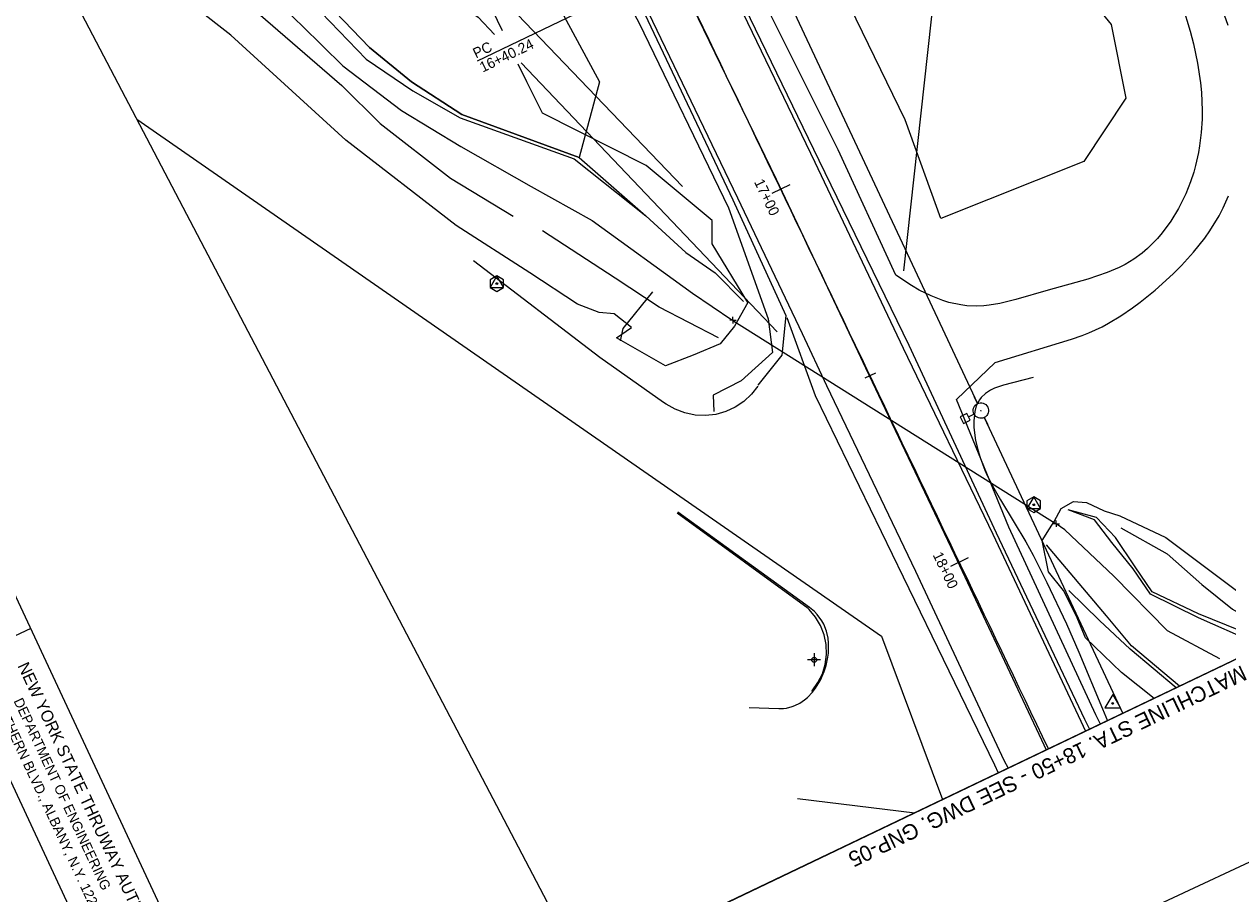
# Model space of a CAD drawing. Extents: x 1040814 to 1041501, y 1126274 to 1127077.
# Drawn here: x 1041061 to 1041352.2, y 1126413.6 to 1126623.9 of the extents above; entities that cross this region are included whole.
import ezdxf

# ---------------------------------------------------------------- set-up
doc = ezdxf.new("R2010")
doc.units = 0
for name, color, linetype in [('AC_P', 7, 'Continuous'), ('ACSC_P_T', 7, 'Continuous'), ('ACSCT_P', 7, 'Continuous'), ('ACSR_P_T', 7, 'Continuous'), ('ACSRT_P', 7, 'Continuous'), ('CBP', 7, 'Continuous'), ('CBS', 7, 'Continuous'), ('clip boundary', 7, 'Continuous'), ('DCP', 7, 'Continuous'), ('DD', 7, 'Continuous'), ('DINV', 7, 'Continuous'), ('LABL', 7, 'Continuous'), ('LAWA', 7, 'Continuous'), ('LAWE', 7, 'Continuous'), ('LELB', 7, 'Continuous'), ('LUKL', 7, 'Continuous'), ('MHB', 7, 'Continuous'), ('NML_P', 7, 'Continuous'), ('NML_P_T', 7, 'Continuous'), ('PE', 7, 'Continuous'), ('PELB', 7, 'Continuous'), ('PSU', 7, 'Continuous'), ('RC', 7, 'Continuous'), ('RDU', 7, 'Continuous'), ('RGB', 7, 'Continuous'), ('S', 7, 'Continuous'), ('SHEET_BORDER', 7, 'Continuous'), ('STDSW', 7, 'Continuous'), ('STDSY', 7, 'Continuous'), ('STFBY', 7, 'Continuous'), ('STSEW', 7, 'Continuous'), ('UEO', 7, 'Continuous'), ('UPL', 7, 'Continuous'), ('USA', 7, 'Continuous')]:
    doc.layers.add(name, color=color, linetype=linetype)

msp = doc.modelspace()

# ---------------------------------------------------------------- linework, layer by layer
at = {"layer": 'AC_P'}
msp.add_arc((951081.07, 1083333.02), 100000, 25.5409537, 25.6611361, dxfattribs=at)
at = {"layer": 'ACSCT_P'}
msp.add_lwpolyline([(1041218.17, 1126637.8), (1041170.58, 1126614.93)], dxfattribs=at)
at = {"layer": 'ACSRT_P'}
for points in [[(1041246.2, 1126584.96), (1041241.87, 1126582.89)], [(1041266.94, 1126539.46), (1041264.35, 1126538.22)], [(1041289.4, 1126494.78), (1041285.07, 1126492.71)], [(1041310.11, 1126449.25), (1041307.51, 1126448.01)]]:
    msp.add_lwpolyline(points, dxfattribs=at)
at = {"layer": 'CBP'}
for points in [[(1041324.33, 1126461.81), (1041322.44, 1126458.54)], [(1041326.22, 1126458.54), (1041324.33, 1126461.81)], [(1041322.44, 1126458.54), (1041326.22, 1126458.54)]]:
    msp.add_lwpolyline(points, dxfattribs=at)
msp.add_circle((1041324.33, 1126459.63), 0.226, dxfattribs=at)
at = {"layer": 'CBS'}
for points in [[(1041175.36, 1126559.22), (1041177, 1126560.17), (1041177, 1126562.06), (1041175.36, 1126563), (1041173.72, 1126562.06), (1041173.72, 1126560.17)], [(1041177, 1126560.17), (1041175.36, 1126563), (1041173.72, 1126560.17)], [(1041305.23, 1126505.78), (1041306.87, 1126506.73), (1041306.87, 1126508.62), (1041305.23, 1126509.56), (1041303.6, 1126508.62), (1041303.6, 1126506.73)], [(1041306.87, 1126506.73), (1041305.23, 1126509.56), (1041303.6, 1126506.73)]]:
    msp.add_lwpolyline(points, close=True, dxfattribs=at)
for centre in [(1041175.36, 1126561.11), (1041305.23, 1126507.67)]:
    msp.add_circle(centre, 0.226, dxfattribs=at)
at = {"layer": 'clip boundary'}
msp.add_lwpolyline([(1041214.88, 1127013.05), (1041436.47, 1126509.64), (1041196.3, 1126394.87), (1040940.57, 1126882.48)], close=True, dxfattribs=at)
at = {"layer": 'DCP'}
msp.add_line((1041232.47, 1126552.24), (1041310.68, 1126503.03), dxfattribs=at)
at = {"layer": 'DD'}
for points in [[(1041074.5, 1126665.52), (1041099.79, 1126648.57), (1041116.42, 1126634.8), (1041128.28, 1126623.45), (1041138.07, 1126613.79), (1041152.29, 1126603.01), (1041166.68, 1126594.25), (1041183.67, 1126584.56), (1041198.44, 1126576.41), (1041222.65, 1126558.83), (1041232.19, 1126552.4)], [(1041312.79, 1126501.59), (1041310.66, 1126503.07)], [(1041350.29, 1126470.43), (1041337.59, 1126477.16), (1041324.61, 1126490.39), (1041312.79, 1126501.59)]]:
    msp.add_lwpolyline(points, dxfattribs=at)
at = {"layer": 'DINV'}
for p, q in [((1041232.47, 1126552.26), (1041231.68, 1126552.26)), ((1041232.47, 1126552.26), (1041232.47, 1126553.05)), ((1041232.47, 1126552.26), (1041233.26, 1126552.26)), ((1041232.47, 1126552.26), (1041232.47, 1126551.48)), ((1041310.66, 1126503.07), (1041310.66, 1126503.85)), ((1041310.66, 1126503.07), (1041309.88, 1126503.07)), ((1041310.66, 1126503.07), (1041311.45, 1126503.07)), ((1041310.66, 1126503.07), (1041310.66, 1126502.28))]:
    msp.add_line(p, q, dxfattribs=at)
at = {"layer": 'LABL'}
msp.add_lwpolyline([(1041253.69, 1126924.89), (1041255.63, 1126894.49), (1041242.19, 1126881.78), (1041242.38, 1126861.25), (1041264.14, 1126852.24), (1041270.04, 1126822.23), (1041258.62, 1126789.97), (1041262.73, 1126771.99), (1041287.02, 1126754.4), (1041303.65, 1126708.97), (1041290.01, 1126684.68), (1041304.47, 1126647.7), (1041323.95, 1126623.76), (1041327.51, 1126605.97), (1041317.37, 1126590.62), (1041282.77, 1126576.87), (1041274.13, 1126600.75), (1041251.99, 1126646.31)], dxfattribs=at)
at = {"layer": 'LAWA'}
for points in [[(1040981.59, 1126825.54), (1041056.77, 1126732.84), (1041104.86, 1126716.99), (1041144.53, 1126704.03), (1041174.4, 1126657.67), (1041200.18, 1126609.9)], [(1041200.18, 1126609.9), (1041195.26, 1126591.63), (1041166.9, 1126602.04), (1041154.69, 1126609.92), (1041144.51, 1126618.19), (1041121.72, 1126641.95), (1041105.83, 1126655.68), (1041077.14, 1126671.62)], [(1041334.37, 1126460.85), (1041326.46, 1126467.11)]]:
    msp.add_lwpolyline(points, dxfattribs=at)
at = {"layer": 'LAWE'}
for points in [[(1041076.45, 1126670.59), (1041104.56, 1126654.96), (1041119.81, 1126640.32), (1041143.71, 1126615.37), (1041155, 1126607.76), (1041166.45, 1126601.18), (1041194.08, 1126591.25), (1041211.38, 1126577.5), (1041221.09, 1126568.66), (1041228.18, 1126563.73), (1041234.99, 1126556.76)], [(1041071.75, 1126659.42), (1041096.69, 1126644.66), (1041137.84, 1126608.98), (1041147.12, 1126599.84), (1041164.12, 1126586.62), (1041179.28, 1126577.39)], [(1041228.94, 1126548.01), (1041214.65, 1126555.44), (1041203.97, 1126562.4), (1041186.38, 1126573.87)], [(1041358.27, 1126474.52), (1041345.09, 1126480.29), (1041333.52, 1126486.04), (1041329.31, 1126492.15), (1041324.1, 1126498.5), (1041319.97, 1126503.98), (1041313.58, 1126506.41)], [(1041340.49, 1126463.77), (1041328.85, 1126473.52), (1041322.86, 1126480.82), (1041308.3, 1126497.94)]]:
    msp.add_lwpolyline(points, dxfattribs=at)
at = {"layer": 'LELB'}
for points in [[(1041220.28, 1126584.56), (1041174.66, 1126632.23), (1041154.91, 1126677.31), (1041125.07, 1126696.32)], [(1041176.7, 1126622.27), (1041171.98, 1126632.18), (1041160.76, 1126642.2), (1041142.54, 1126665.23), (1041113.63, 1126673.96), (1041085.87, 1126690.6)], [(1041077.14, 1126671.62), (1041105.83, 1126655.68), (1041121.72, 1126641.95), (1041144.51, 1126618.19), (1041154.69, 1126609.92), (1041166.9, 1126602.04), (1041195.26, 1126591.63), (1041211.38, 1126577.5), (1041221.09, 1126568.66), (1041228.18, 1126563.73), (1041234.99, 1126556.76)], [(1041236.11, 1126556.56), (1041232.82, 1126550.8), (1041229.37, 1126546.59), (1041222.82, 1126543.78), (1041216.12, 1126541.2), (1041204.33, 1126547.99), (1041207.93, 1126550.54), (1041203.7, 1126553.78), (1041200.07, 1126554.14), (1041194.88, 1126556.12), (1041183.33, 1126563.71), (1041165.53, 1126575.17), (1041138.79, 1126595.82), (1041110.99, 1126621.22), (1041084.42, 1126641.97), (1041062.93, 1126656.21)], [(1041236.11, 1126556.56), (1041227.44, 1126570.71), (1041227.44, 1126576.36), (1041211.48, 1126589.66), (1041186.38, 1126602.31), (1041182.57, 1126609.94), (1041180.55, 1126614.2)], [(1041334.37, 1126460.85), (1041326.46, 1126467.11), (1041317.72, 1126475.49), (1041315.51, 1126480.89), (1041312.47, 1126486.91), (1041308.79, 1126491.43), (1041307.3, 1126499), (1041309.01, 1126501.86), (1041310.14, 1126503.62), (1041311.9, 1126506.77), (1041314.86, 1126508.46), (1041317.98, 1126508.18), (1041322.26, 1126506.19), (1041326.05, 1126505.01), (1041337.16, 1126499.74), (1041357.15, 1126484.76)], [(1041358.63, 1126475.84), (1041345.13, 1126481.25), (1041333.9, 1126486.59), (1041329.81, 1126492.61), (1041325, 1126499.74), (1041320.38, 1126504.55), (1041313.58, 1126506.41)], [(1041326.28, 1126502.08), (1041337.5, 1126495.77), (1041345.92, 1126488.36), (1041353.29, 1126482.37), (1041361.08, 1126477.94)], [(1041339.73, 1126463.41), (1041328.56, 1126472.74), (1041321.18, 1126479.68), (1041313.72, 1126486.96)]]:
    msp.add_lwpolyline(points, dxfattribs=at)
at = {"layer": 'LUKL'}
msp.add_lwpolyline([(1041212.99, 1126559.11), (1041205.81, 1126550.25), (1041205.17, 1126547.32)], dxfattribs=at)
at = {"layer": 'MHB'}
for points in [[(1041273.77, 1126564.22), (1041288, 1126693.29), (1041193.5, 1127002.88)], [(1040943.43, 1126883.84), (1041077.77, 1126691.61), (1041170.82, 1126625.52), (1041174.77, 1126621.37)], [(1041181.26, 1126614.53), (1041243.16, 1126549.42)]]:
    msp.add_lwpolyline(points, dxfattribs=at)
at = {"layer": 'NML_P'}
msp.add_line((1041196.3, 1126394.87), (1041436.47, 1126509.64), dxfattribs=at)
at = {"layer": 'PE'}
for points in [[(1041081.62, 1126949.62), (1041102.41, 1126905.66), (1041123.97, 1126860.46), (1041145.4, 1126815.4), (1041166.83, 1126770.22), (1041188.29, 1126725.66), (1041210.14, 1126680.18), (1041231.44, 1126635.95), (1041253.25, 1126591), (1041274.98, 1126546.22), (1041296.15, 1126500.9), (1041317.55, 1126455.84), (1041318.73, 1126453.38)], [(1041061.22, 1126939.91), (1041082.3, 1126895.54), (1041103.78, 1126850.36), (1041125.11, 1126805.74), (1041146.56, 1126760.22), (1041167.95, 1126715.79), (1041189.67, 1126670.72), (1041211.13, 1126626.27), (1041232.46, 1126581.39), (1041245.23, 1126553.4), (1041244.27, 1126543.82), (1041238.51, 1126536.54)], [(1041238.47, 1126536.35), (1041236.93, 1126534.37), (1041235.09, 1126532.65), (1041233, 1126531.25), (1041230.72, 1126530.19), (1041228.3, 1126529.51), (1041225.8, 1126529.22), (1041223.29, 1126529.33), (1041220.82, 1126529.84), (1041218.47, 1126530.73), (1041216.29, 1126531.98), (1041215.69, 1126532.4), (1041200.29, 1126543.22), (1041169.71, 1126566.62)], [(1041236.38, 1126458.64), (1041243.6, 1126458.39), (1041244.73, 1126458.42), (1041245.46, 1126458.51), (1041246.82, 1126458.85), (1041247.46, 1126459.09), (1041248.67, 1126459.71), (1041249.78, 1126460.48), (1041250.47, 1126461.07), (1041251.71, 1126462.37), (1041252.41, 1126463.28), (1041253.62, 1126465.22), (1041254.55, 1126467.32), (1041255.02, 1126468.78), (1041255.44, 1126470.78), (1041255.56, 1126471.79), (1041255.61, 1126474.19), (1041255.49, 1126475.37), (1041255.1, 1126477.12), (1041254.44, 1126478.79), (1041254, 1126479.6), (1041252.87, 1126481.12), (1041252.18, 1126481.83), (1041250.98, 1126482.83), (1041219.1, 1126505.9)], [(1041248.06, 1126436.61), (1041276.51, 1126433.2)]]:
    msp.add_lwpolyline(points, dxfattribs=at)
at = {"layer": 'PELB'}
msp.add_lwpolyline([(1041245.51, 1126552.89), (1041252.33, 1126534.08), (1041273.63, 1126490.24), (1041295.72, 1126444.79), (1041296.6, 1126442.8)], dxfattribs=at)
at = {"layer": 'PSU'}
for points in [[(1041271.9, 1126563.2), (1041257.91, 1126593.44), (1041235.69, 1126638.05), (1041214.95, 1126682.34), (1041193.32, 1126727.74), (1041171.68, 1126772.68), (1041150.4, 1126817.33), (1041128.89, 1126862.55), (1041107.28, 1126907.69), (1041105.25, 1126911.9)], [(1041075.19, 1126898.29), (1041078.06, 1126892.31), (1041099.27, 1126847.58), (1041120.87, 1126802.65), (1041142.35, 1126757.81), (1041163.59, 1126712.68), (1041185.79, 1126668.17), (1041209.73, 1126624.25), (1041231.42, 1126579.4), (1041240.95, 1126552.57), (1041242.07, 1126544.47), (1041234.49, 1126537.64), (1041227.67, 1126534.18), (1041227.86, 1126530.17)], [(1041321.36, 1126454.63), (1041320.24, 1126456.9), (1041299.25, 1126502.25), (1041286.53, 1126533.1)]]:
    msp.add_lwpolyline(points, dxfattribs=at)
at = {"layer": 'RC'}
msp.add_lwpolyline([(1041251.71, 1126462.37), (1041251.62, 1126462.7), (1041253.04, 1126464.64), (1041254.11, 1126466.78), (1041254.81, 1126469.07), (1041255.13, 1126471.45), (1041255.04, 1126473.85), (1041254.56, 1126476.2), (1041253.69, 1126478.43), (1041252.47, 1126480.5), (1041250.92, 1126482.33), (1041250.68, 1126482.55), (1041218.94, 1126505.61)], dxfattribs=at)
at = {"layer": 'RDU'}
for points in [[(1041341.2, 1126628.29), (1041343.06, 1126622.18), (1041343.86, 1126619.09), (1041344.87, 1126614.41), (1041345.58, 1126609.68), (1041345.81, 1126607.31), (1041346, 1126603.01), (1041345.97, 1126600.86), (1041345.77, 1126597.63), (1041345.37, 1126594.42), (1041345.09, 1126592.82), (1041344.37, 1126589.65), (1041343.93, 1126588.07), (1041343.16, 1126585.73), (1041342, 1126582.8), (1041341.34, 1126581.36), (1041340.25, 1126579.25), (1041338.41, 1126576.21), (1041336.33, 1126573.38), (1041335.2, 1126572.05), (1041332.76, 1126569.6), (1041331.46, 1126568.49), (1041329.41, 1126566.99), (1041327.36, 1126565.76), (1041325.94, 1126565.03), (1041323, 1126563.77), (1041318.36, 1126562.22), (1041308.7, 1126559.57), (1041300.88, 1126557.25), (1041297.02, 1126556.32), (1041294.46, 1126555.89), (1041293.19, 1126555.76), (1041291.29, 1126555.68), (1041289.09, 1126555.77), (1041287.63, 1126555.95), (1041284.72, 1126556.57), (1041283.27, 1126557.01), (1041280.4, 1126558.13), (1041277.54, 1126559.55), (1041275.65, 1126560.65), (1041271.9, 1126563.2)], [(1041352.25, 1126623.54), (1041350.5, 1126628.52)], [(1041286.53, 1126533.1), (1041295.87, 1126542.03), (1041314.39, 1126547.7), (1041316.95, 1126548.57), (1041318.6, 1126549.23), (1041321.78, 1126550.7), (1041323.32, 1126551.52), (1041326.3, 1126553.3), (1041329.16, 1126555.25), (1041331.02, 1126556.63), (1041334.64, 1126559.57), (1041338.94, 1126563.46), (1041340.99, 1126565.52), (1041343.92, 1126568.74), (1041346.61, 1126572.13), (1041347.85, 1126573.89), (1041350.09, 1126577.54), (1041351.08, 1126579.43), (1041352.38, 1126582.35)]]:
    msp.add_lwpolyline(points, dxfattribs=at)
at = {"layer": 'RGB'}
msp.add_lwpolyline([(1041305.06, 1126538.43), (1041297.9, 1126536.53), (1041295.73, 1126535.8), (1041294.78, 1126535.35), (1041293.54, 1126534.56), (1041292.53, 1126533.6), (1041292.11, 1126533.05), (1041291.61, 1126532.17), (1041291.34, 1126531.53), (1041290.97, 1126530.16), (1041290.73, 1126527.92), (1041290.77, 1126526.35), (1041291.18, 1126523.19), (1041291.76, 1126520.69), (1041292.24, 1126519.08), (1041293.41, 1126516.01), (1041294.09, 1126514.53), (1041295.56, 1126511.66), (1041297.17, 1126508.88), (1041300.52, 1126503.4), (1041303.29, 1126498.66), (1041305.06, 1126495.44), (1041308.43, 1126488.89), (1041313.14, 1126478.84), (1041316.12, 1126472.03), (1041321.85, 1126458.29), (1041323.04, 1126455.44)], dxfattribs=at)
at = {"layer": 'S'}
for p, q in [((1041252.11, 1126471.74), (1041252.11, 1126468.59)), ((1041253.69, 1126470.17), (1041250.54, 1126470.17))]:
    msp.add_line(p, q, dxfattribs=at)
msp.add_circle((1041252.11, 1126470.17), 0.591, dxfattribs=at)
at = {"layer": 'SHEET_BORDER'}
for p, q in [((1041137.06, 1126318.3), (1040994.93, 1126622.55)), ((1041062.6, 1126477.7), (1041026.36, 1126460.77)), ((1041105.32, 1126338.99), (1041044.48, 1126469.23))]:
    msp.add_line(p, q, dxfattribs=at)
msp.add_lwpolyline([(1041103.08, 1126302.42), (1041099.76, 1126303.63), (1040835.24, 1126869.9), (1040836.45, 1126873.22), (1041211.88, 1127048.6), (1041215.2, 1127047.39), (1041479.72, 1126481.12), (1041478.52, 1126477.8)], close=True, dxfattribs=at)
at = {"layer": 'STDSW'}
msp.add_lwpolyline([(1041249.19, 1126549.07), (1041255.07, 1126536.49), (1041276.6, 1126491.6), (1041298.01, 1126445.88), (1041299.01, 1126443.95)], dxfattribs=at)
at = {"layer": 'STDSY'}
msp.add_lwpolyline([(1041262.65, 1126544.69), (1041264.54, 1126540.79), (1041285.98, 1126495.73), (1041307.1, 1126450.79), (1041308.28, 1126448.38)], dxfattribs=at)
at = {"layer": 'STFBY'}
msp.add_lwpolyline([(1041071.47, 1126944.79), (1041092.31, 1126900.59), (1041114.11, 1126855.47), (1041135.17, 1126810.47), (1041156.8, 1126765.46), (1041178.14, 1126720.76), (1041199.95, 1126675.44), (1041221.33, 1126630.97), (1041242.89, 1126586.34), (1041262.65, 1126544.69)], dxfattribs=at)
at = {"layer": 'STSEW'}
for points in [[(1041080.88, 1126949.27), (1041101.64, 1126905.36), (1041123.25, 1126860.06), (1041144.5, 1126815.03), (1041166.26, 1126769.97), (1041187.32, 1126725.16), (1041209.31, 1126679.76), (1041230.58, 1126635.5), (1041252.28, 1126590.51), (1041273.68, 1126545.52), (1041295.33, 1126500.52), (1041316.59, 1126455.37), (1041317.78, 1126452.92)], [(1041062.04, 1126940.3), (1041083.12, 1126896.06), (1041104.75, 1126850.88), (1041125.82, 1126806.14), (1041147.63, 1126760.76), (1041168.87, 1126716.25), (1041190.63, 1126671.14), (1041211.99, 1126626.71), (1041233.6, 1126581.88), (1041249.19, 1126549.07)]]:
    msp.add_lwpolyline(points, dxfattribs=at)
at = {"layer": 'UEO'}
for points in [[(1041209.06, 1126708.25), (1041291.64, 1126532.14)], [(1041293.24, 1126528.73), (1041326.75, 1126457.21)]]:
    msp.add_lwpolyline(points, dxfattribs=at)
at = {"layer": 'UPL'}
for p, q in [((1041290.77, 1126533.8), (1041291.61, 1126532.12)), ((1041292.33, 1126530.47), (1041292.55, 1126530.4)), ((1041292.4, 1126530.32), (1041292.48, 1126530.55)), ((1041289.43, 1126528.93), (1041290.76, 1126529.59)), ((1041293.28, 1126528.75), (1041294.11, 1126527.07))]:
    msp.add_line(p, q, dxfattribs=at)
msp.add_lwpolyline([(1041287.43, 1126528.93), (1041288.23, 1126527.33), (1041289.82, 1126528.13), (1041289.03, 1126529.73)], close=True, dxfattribs=at)
msp.add_ellipse((1041292.44, 1126530.43), major_axis=(0.92, 1.64), ratio=0.998335, dxfattribs=at)
at = {"layer": 'USA'}
for p, q in [((1041088.27, 1126600.85), (1041268.42, 1126475.85)), ((1041268.42, 1126475.85), (1041283.18, 1126436.39))]:
    msp.add_line(p, q, dxfattribs=at)

# ---------------------------------------------------------------- texts
at = {"layer": 'ACSC_P_T'}
for s, p in [('16+40.24', (1041171.93, 1126612.12)), ('PC', (1041170.31, 1126615.5))]:
    msp.add_text(s, height=2.496, rotation=25.6611, dxfattribs=at).set_placement(p)
at = {"layer": 'ACSR_P_T'}
for s, rotation, p in [('17+00', 295.6269, (1041237.54, 1126585.7)), ('18+00', 295.5696, (1041280.75, 1126495.52))]:
    msp.add_text(s, height=2.496, rotation=rotation, dxfattribs=at).set_placement(p)
at = {"layer": 'NML_P_T'}
msp.add_text('MATCHLINE STA. 18+50 - SEE DWG. GNP-05', height=3.744, rotation=205.541, dxfattribs=at).set_placement((1041355.53, 1126468.94))
at = {"layer": 'SHEET_BORDER'}
for s, height, p in [('NEW YORK STATE THRUWAY AUTHORITY', 2.88, (1041059.35, 1126468.74)), ('200 SOUTHERN BLVD., ALBANY, N.Y. 12209', 2.4, (1041050, 1126467.76)), ('DEPARTMENT OF ENGINEERING', 2.4, (1041058.4, 1126460.23))]:
    msp.add_text(s, height=height, rotation=295.0387, dxfattribs=at).set_placement(p)

doc.saveas('drawing.dxf')
